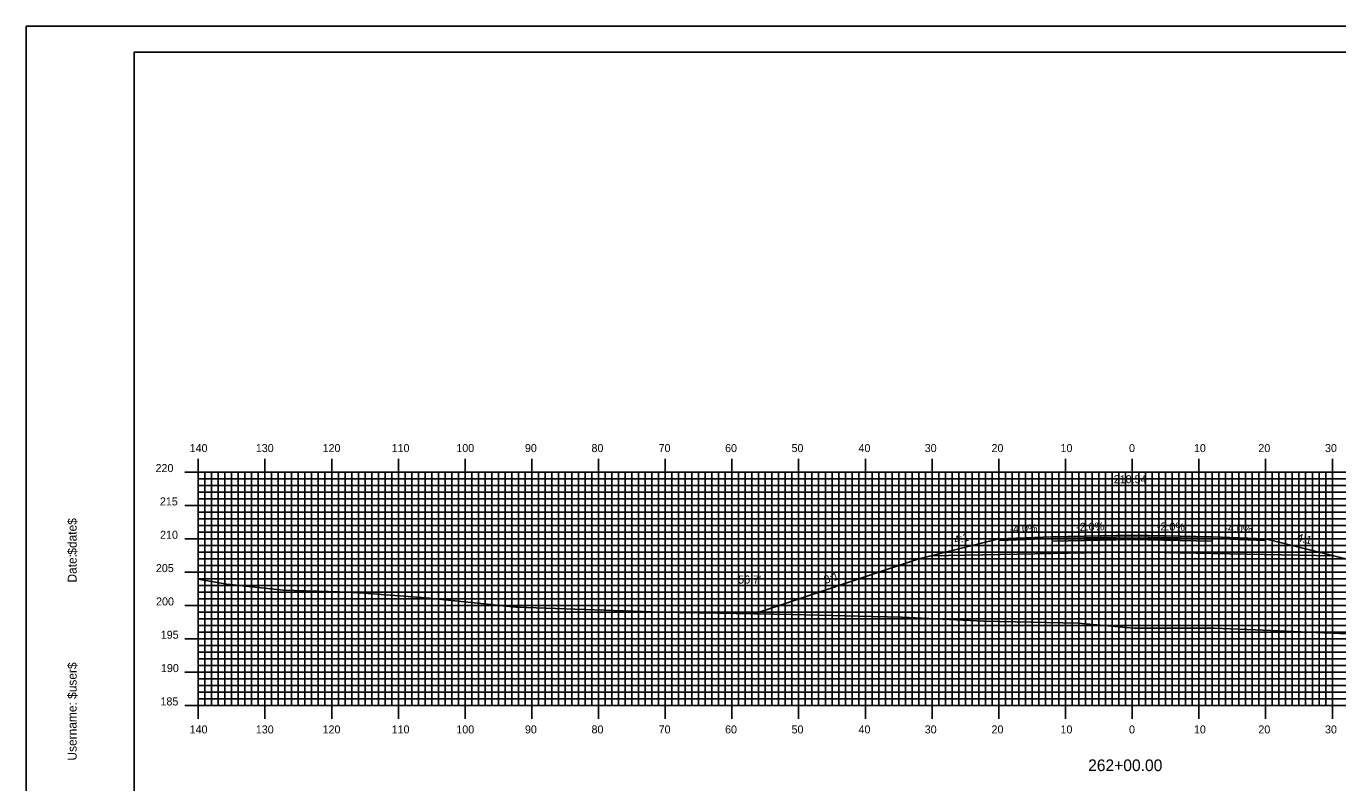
# Model space of a CAD drawing. Extents: x 1806258 to 1806601, y 442591 to 442811.
# Drawn here: x 1806257.9 to 1806454.5, y 442697.1 to 442810.5 of the extents above; entities that cross this region are included whole.
import ezdxf

# ---------------------------------------------------------------- set-up
doc = ezdxf.new("R2010")
doc.units = 0
for name, color, linetype in [('ANNOTATION', 7, 'Continuous'), ('BORDER', 7, 'Continuous'), ('D_Roadway_Centerline', 7, 'Continuous'), ('D_Roadway_Centerline_Text', 7, 'Continuous'), ('D_Roadway_Edge_Shoulder', 7, 'Continuous'), ('D_Roadway_Edge_TW', 7, 'Continuous'), ('D_Roadway_Pavement', 7, 'Continuous'), ('D_Roadway_SlopeLines', 7, 'Continuous'), ('D_Roadway_SubGrade', 7, 'Continuous'), ('D_Text_Standard', 7, 'Continuous'), ('H_V ANNOTATION', 7, 'Continuous'), ('MAJOR', 7, 'Continuous'), ('MINOR', 7, 'Continuous'), ('PLOT BOUNDARY', 7, 'Continuous'), ('S_Roadway_Centerline', 7, 'Continuous')]:
    doc.layers.add(name, color=color, linetype=linetype)

msp = doc.modelspace()

# ---------------------------------------------------------------- linework, layer by layer
at = {"layer": 'BORDER'}
msp.add_lwpolyline([(1806274.13, 442596.67), (1806594.13, 442596.67), (1806594.13, 442806.67), (1806274.13, 442806.67)], close=True, dxfattribs=at)
at = {"layer": 'D_Roadway_Centerline'}
msp.add_lwpolyline([(1806367.07, 442722.43), (1806391.73, 442730.65), (1806393.56, 442731.1), (1806403.73, 442733.65), (1806411.73, 442733.97), (1806423.73, 442734.21), (1806435.73, 442733.97), (1806443.73, 442733.65), (1806453.91, 442731.1), (1806455.73, 442730.65), (1806492.1, 442718.53)], dxfattribs=at)
at = {"layer": 'D_Roadway_Edge_Shoulder'}
for points in [[(1806411.73, 442733.97), (1806403.73, 442733.65), (1806403.73, 442733.4), (1806411.73, 442733.72)], [(1806435.73, 442733.97), (1806443.73, 442733.65), (1806443.73, 442733.4), (1806435.73, 442733.72)]]:
    msp.add_lwpolyline(points, close=True, dxfattribs=at)
at = {"layer": 'D_Roadway_Edge_TW'}
msp.add_lwpolyline([(1806411.73, 442733.72), (1806411.73, 442733.97), (1806423.73, 442734.21), (1806435.73, 442733.97), (1806435.73, 442733.72), (1806423.73, 442733.96)], close=True, dxfattribs=at)
at = {"layer": 'D_Roadway_Pavement'}
msp.add_lwpolyline([(1806411.73, 442733.3), (1806411.73, 442733.72), (1806423.73, 442733.96), (1806435.73, 442733.72), (1806435.73, 442733.3), (1806423.73, 442733.54)], close=True, dxfattribs=at)
at = {"layer": 'D_Roadway_SlopeLines'}
for points in [[(1806403.73, 442733.65), (1806391.73, 442730.65), (1806367.07, 442722.43)], [(1806443.73, 442733.65), (1806455.73, 442730.65), (1806492.1, 442718.53)]]:
    msp.add_lwpolyline(points, dxfattribs=at)
at = {"layer": 'D_Roadway_SubGrade'}
msp.add_lwpolyline([(1806411.73, 442731.47), (1806393.56, 442731.1), (1806403.73, 442733.65), (1806403.73, 442733.4), (1806411.73, 442733.72), (1806423.73, 442733.96), (1806435.73, 442733.72), (1806443.73, 442733.4), (1806443.73, 442733.65), (1806453.91, 442731.1), (1806435.73, 442731.47), (1806423.73, 442731.71)], close=True, dxfattribs=at)
at = {"layer": 'MAJOR'}
for p, q in [((1806283.73, 442745.67), (1806283.73, 442743.67)), ((1806293.73, 442745.67), (1806293.73, 442743.67)), ((1806303.73, 442745.67), (1806303.73, 442743.67)), ((1806313.73, 442745.67), (1806313.73, 442743.67)), ((1806323.73, 442745.67), (1806323.73, 442743.67)), ((1806333.73, 442745.67), (1806333.73, 442743.67)), ((1806343.73, 442745.67), (1806343.73, 442743.67)), ((1806353.73, 442745.67), (1806353.73, 442743.67)), ((1806363.73, 442745.67), (1806363.73, 442743.67)), ((1806373.73, 442745.67), (1806373.73, 442743.67)), ((1806383.73, 442745.67), (1806383.73, 442743.67)), ((1806393.73, 442745.67), (1806393.73, 442743.67)), ((1806403.73, 442745.67), (1806403.73, 442743.67)), ((1806413.73, 442745.67), (1806413.73, 442743.67)), ((1806423.73, 442745.67), (1806423.73, 442743.67)), ((1806433.73, 442745.67), (1806433.73, 442743.67)), ((1806443.73, 442745.67), (1806443.73, 442743.67)), ((1806453.73, 442745.67), (1806453.73, 442743.67)), ((1806281.73, 442743.67), (1806283.73, 442743.67)), ((1806283.73, 442743.67), (1806563.73, 442743.67)), ((1806283.73, 442708.67), (1806283.73, 442743.67)), ((1806283.73, 442708.67), (1806283.73, 442743.67)), ((1806283.73, 442743.67), (1806563.73, 442743.67)), ((1806293.73, 442708.67), (1806293.73, 442743.67)), ((1806303.73, 442708.67), (1806303.73, 442743.67)), ((1806313.73, 442708.67), (1806313.73, 442743.67)), ((1806323.73, 442708.67), (1806323.73, 442743.67)), ((1806333.73, 442708.67), (1806333.73, 442743.67)), ((1806343.73, 442708.67), (1806343.73, 442743.67)), ((1806353.73, 442708.67), (1806353.73, 442743.67)), ((1806363.73, 442708.67), (1806363.73, 442743.67)), ((1806373.73, 442708.67), (1806373.73, 442743.67)), ((1806383.73, 442708.67), (1806383.73, 442743.67)), ((1806393.73, 442708.67), (1806393.73, 442743.67)), ((1806403.73, 442708.67), (1806403.73, 442743.67)), ((1806413.73, 442708.67), (1806413.73, 442743.67)), ((1806423.73, 442708.67), (1806423.73, 442743.67)), ((1806433.73, 442708.67), (1806433.73, 442743.67)), ((1806443.73, 442708.67), (1806443.73, 442743.67)), ((1806453.73, 442708.67), (1806453.73, 442743.67)), ((1806281.73, 442738.67), (1806283.73, 442738.67)), ((1806283.73, 442738.67), (1806563.73, 442738.67)), ((1806281.73, 442733.67), (1806283.73, 442733.67)), ((1806283.73, 442733.67), (1806563.73, 442733.67)), ((1806281.73, 442728.67), (1806283.73, 442728.67)), ((1806283.73, 442728.67), (1806563.73, 442728.67)), ((1806281.73, 442723.67), (1806283.73, 442723.67)), ((1806283.73, 442723.67), (1806563.73, 442723.67)), ((1806281.73, 442718.67), (1806283.73, 442718.67)), ((1806283.73, 442718.67), (1806563.73, 442718.67)), ((1806281.73, 442713.67), (1806283.73, 442713.67)), ((1806283.73, 442713.67), (1806563.73, 442713.67)), ((1806281.73, 442708.67), (1806283.73, 442708.67)), ((1806283.73, 442708.67), (1806563.73, 442708.67)), ((1806283.73, 442708.67), (1806563.73, 442708.67)), ((1806283.73, 442706.66), (1806283.73, 442708.67)), ((1806293.73, 442706.66), (1806293.73, 442708.67)), ((1806303.73, 442706.66), (1806303.73, 442708.67)), ((1806313.73, 442706.66), (1806313.73, 442708.67)), ((1806323.73, 442706.66), (1806323.73, 442708.67)), ((1806333.73, 442706.66), (1806333.73, 442708.67)), ((1806343.73, 442706.66), (1806343.73, 442708.67)), ((1806353.73, 442706.66), (1806353.73, 442708.67)), ((1806363.73, 442706.66), (1806363.73, 442708.67)), ((1806373.73, 442706.66), (1806373.73, 442708.67)), ((1806383.73, 442706.66), (1806383.73, 442708.67)), ((1806393.73, 442706.66), (1806393.73, 442708.67)), ((1806403.73, 442706.66), (1806403.73, 442708.67)), ((1806413.73, 442706.66), (1806413.73, 442708.67)), ((1806423.73, 442706.66), (1806423.73, 442708.67)), ((1806433.73, 442706.66), (1806433.73, 442708.67)), ((1806443.73, 442706.66), (1806443.73, 442708.67)), ((1806453.73, 442706.66), (1806453.73, 442708.67))]:
    msp.add_line(p, q, dxfattribs=at)
at = {"layer": 'MINOR'}
for p, q in [((1806284.73, 442708.67), (1806284.73, 442743.67)), ((1806285.73, 442708.67), (1806285.73, 442743.67)), ((1806286.73, 442708.67), (1806286.73, 442743.67)), ((1806287.73, 442708.67), (1806287.73, 442743.67)), ((1806288.73, 442708.67), (1806288.73, 442743.67)), ((1806289.73, 442708.67), (1806289.73, 442743.67)), ((1806290.73, 442708.67), (1806290.73, 442743.67)), ((1806291.73, 442708.67), (1806291.73, 442743.67)), ((1806292.73, 442708.67), (1806292.73, 442743.67)), ((1806294.73, 442708.67), (1806294.73, 442743.67)), ((1806295.73, 442708.67), (1806295.73, 442743.67)), ((1806296.73, 442708.67), (1806296.73, 442743.67)), ((1806297.73, 442708.67), (1806297.73, 442743.67)), ((1806298.73, 442708.67), (1806298.73, 442743.67)), ((1806299.73, 442708.67), (1806299.73, 442743.67)), ((1806300.73, 442708.67), (1806300.73, 442743.67)), ((1806301.73, 442708.67), (1806301.73, 442743.67)), ((1806302.73, 442708.67), (1806302.73, 442743.67)), ((1806304.73, 442708.67), (1806304.73, 442743.67)), ((1806305.73, 442708.67), (1806305.73, 442743.67)), ((1806306.73, 442708.67), (1806306.73, 442743.67)), ((1806307.73, 442708.67), (1806307.73, 442743.67)), ((1806308.73, 442708.67), (1806308.73, 442743.67)), ((1806309.73, 442708.67), (1806309.73, 442743.67)), ((1806310.73, 442708.67), (1806310.73, 442743.67)), ((1806311.73, 442708.67), (1806311.73, 442743.67)), ((1806312.73, 442708.67), (1806312.73, 442743.67)), ((1806314.73, 442708.67), (1806314.73, 442743.67)), ((1806315.73, 442708.67), (1806315.73, 442743.67)), ((1806316.73, 442708.67), (1806316.73, 442743.67)), ((1806317.73, 442708.67), (1806317.73, 442743.67)), ((1806318.73, 442708.67), (1806318.73, 442743.67)), ((1806319.73, 442708.67), (1806319.73, 442743.67)), ((1806320.73, 442708.67), (1806320.73, 442743.67)), ((1806321.73, 442708.67), (1806321.73, 442743.67)), ((1806322.73, 442708.67), (1806322.73, 442743.67)), ((1806324.73, 442708.67), (1806324.73, 442743.67)), ((1806325.73, 442708.67), (1806325.73, 442743.67)), ((1806326.73, 442708.67), (1806326.73, 442743.67)), ((1806327.73, 442708.67), (1806327.73, 442743.67)), ((1806328.73, 442708.67), (1806328.73, 442743.67)), ((1806329.73, 442708.67), (1806329.73, 442743.67)), ((1806330.73, 442708.67), (1806330.73, 442743.67)), ((1806331.73, 442708.67), (1806331.73, 442743.67)), ((1806332.73, 442708.67), (1806332.73, 442743.67)), ((1806334.73, 442708.67), (1806334.73, 442743.67)), ((1806335.73, 442708.67), (1806335.73, 442743.67)), ((1806336.73, 442708.67), (1806336.73, 442743.67)), ((1806337.73, 442708.67), (1806337.73, 442743.67)), ((1806338.73, 442708.67), (1806338.73, 442743.67)), ((1806339.73, 442708.67), (1806339.73, 442743.67)), ((1806340.73, 442708.67), (1806340.73, 442743.67)), ((1806341.73, 442708.67), (1806341.73, 442743.67)), ((1806342.73, 442708.67), (1806342.73, 442743.67)), ((1806344.73, 442708.67), (1806344.73, 442743.67)), ((1806345.73, 442708.67), (1806345.73, 442743.67)), ((1806346.73, 442708.67), (1806346.73, 442743.67)), ((1806347.73, 442708.67), (1806347.73, 442743.67)), ((1806348.73, 442708.67), (1806348.73, 442743.67)), ((1806349.73, 442708.67), (1806349.73, 442743.67)), ((1806350.73, 442708.67), (1806350.73, 442743.67)), ((1806351.73, 442708.67), (1806351.73, 442743.67)), ((1806352.73, 442708.67), (1806352.73, 442743.67)), ((1806354.73, 442708.67), (1806354.73, 442743.67)), ((1806355.73, 442708.67), (1806355.73, 442743.67)), ((1806356.73, 442708.67), (1806356.73, 442743.67)), ((1806357.73, 442708.67), (1806357.73, 442743.67)), ((1806358.73, 442708.67), (1806358.73, 442743.67)), ((1806359.73, 442708.67), (1806359.73, 442743.67)), ((1806360.73, 442708.67), (1806360.73, 442743.67)), ((1806361.73, 442708.67), (1806361.73, 442743.67)), ((1806362.73, 442708.67), (1806362.73, 442743.67)), ((1806364.73, 442708.67), (1806364.73, 442743.67)), ((1806365.73, 442708.67), (1806365.73, 442743.67)), ((1806366.73, 442708.67), (1806366.73, 442743.67)), ((1806367.73, 442708.67), (1806367.73, 442743.67)), ((1806368.73, 442708.67), (1806368.73, 442743.67)), ((1806369.73, 442708.67), (1806369.73, 442743.67)), ((1806370.73, 442708.67), (1806370.73, 442743.67)), ((1806371.73, 442708.67), (1806371.73, 442743.67)), ((1806372.73, 442708.67), (1806372.73, 442743.67)), ((1806374.73, 442708.67), (1806374.73, 442743.67)), ((1806375.73, 442708.67), (1806375.73, 442743.67)), ((1806376.73, 442708.67), (1806376.73, 442743.67)), ((1806377.73, 442708.67), (1806377.73, 442743.67)), ((1806378.73, 442708.67), (1806378.73, 442743.67)), ((1806379.73, 442708.67), (1806379.73, 442743.67)), ((1806380.73, 442708.67), (1806380.73, 442743.67)), ((1806381.73, 442708.67), (1806381.73, 442743.67)), ((1806382.73, 442708.67), (1806382.73, 442743.67)), ((1806384.73, 442708.67), (1806384.73, 442743.67)), ((1806385.73, 442708.67), (1806385.73, 442743.67)), ((1806386.73, 442708.67), (1806386.73, 442743.67)), ((1806387.73, 442708.67), (1806387.73, 442743.67)), ((1806388.73, 442708.67), (1806388.73, 442743.67)), ((1806389.73, 442708.67), (1806389.73, 442743.67)), ((1806390.73, 442708.67), (1806390.73, 442743.67)), ((1806391.73, 442708.67), (1806391.73, 442743.67)), ((1806392.73, 442708.67), (1806392.73, 442743.67)), ((1806394.73, 442708.67), (1806394.73, 442743.67)), ((1806395.73, 442708.67), (1806395.73, 442743.67)), ((1806396.73, 442708.67), (1806396.73, 442743.67)), ((1806397.73, 442708.67), (1806397.73, 442743.67)), ((1806398.73, 442708.67), (1806398.73, 442743.67)), ((1806399.73, 442708.67), (1806399.73, 442743.67)), ((1806400.73, 442708.67), (1806400.73, 442743.67)), ((1806401.73, 442708.67), (1806401.73, 442743.67)), ((1806402.73, 442708.67), (1806402.73, 442743.67)), ((1806404.73, 442708.67), (1806404.73, 442743.67)), ((1806405.73, 442708.67), (1806405.73, 442743.67)), ((1806406.73, 442708.67), (1806406.73, 442743.67)), ((1806407.73, 442708.67), (1806407.73, 442743.67)), ((1806408.73, 442708.67), (1806408.73, 442743.67)), ((1806409.73, 442708.67), (1806409.73, 442743.67)), ((1806410.73, 442708.67), (1806410.73, 442743.67)), ((1806411.73, 442708.67), (1806411.73, 442743.67)), ((1806412.73, 442708.67), (1806412.73, 442743.67)), ((1806414.73, 442708.67), (1806414.73, 442743.67)), ((1806415.73, 442708.67), (1806415.73, 442743.67)), ((1806416.73, 442708.67), (1806416.73, 442743.67)), ((1806417.73, 442708.67), (1806417.73, 442743.67)), ((1806418.73, 442708.67), (1806418.73, 442743.67)), ((1806419.73, 442708.67), (1806419.73, 442743.67)), ((1806420.73, 442708.67), (1806420.73, 442743.67)), ((1806421.73, 442708.67), (1806421.73, 442743.67)), ((1806422.73, 442708.67), (1806422.73, 442743.67)), ((1806424.73, 442708.67), (1806424.73, 442743.67)), ((1806425.73, 442708.67), (1806425.73, 442743.67)), ((1806426.73, 442708.67), (1806426.73, 442743.67)), ((1806427.73, 442708.67), (1806427.73, 442743.67)), ((1806428.73, 442708.67), (1806428.73, 442743.67)), ((1806429.73, 442708.67), (1806429.73, 442743.67)), ((1806430.73, 442708.67), (1806430.73, 442743.67)), ((1806431.73, 442708.67), (1806431.73, 442743.67)), ((1806432.73, 442708.67), (1806432.73, 442743.67)), ((1806434.73, 442708.67), (1806434.73, 442743.67)), ((1806435.73, 442708.67), (1806435.73, 442743.67)), ((1806436.73, 442708.67), (1806436.73, 442743.67)), ((1806437.73, 442708.67), (1806437.73, 442743.67)), ((1806438.73, 442708.67), (1806438.73, 442743.67)), ((1806439.73, 442708.67), (1806439.73, 442743.67)), ((1806440.73, 442708.67), (1806440.73, 442743.67)), ((1806441.73, 442708.67), (1806441.73, 442743.67)), ((1806442.73, 442708.67), (1806442.73, 442743.67)), ((1806444.73, 442708.67), (1806444.73, 442743.67)), ((1806445.73, 442708.67), (1806445.73, 442743.67)), ((1806446.73, 442708.67), (1806446.73, 442743.67)), ((1806447.73, 442708.67), (1806447.73, 442743.67)), ((1806448.73, 442708.67), (1806448.73, 442743.67)), ((1806449.73, 442708.67), (1806449.73, 442743.67)), ((1806450.73, 442708.67), (1806450.73, 442743.67)), ((1806451.73, 442708.67), (1806451.73, 442743.67)), ((1806452.73, 442708.67), (1806452.73, 442743.67)), ((1806283.73, 442742.67), (1806563.73, 442742.67)), ((1806283.73, 442742.67), (1806285.74, 442742.67)), ((1806283.73, 442741.67), (1806563.73, 442741.67)), ((1806283.73, 442741.67), (1806285.74, 442741.67)), ((1806283.73, 442740.67), (1806563.73, 442740.67)), ((1806283.73, 442740.67), (1806285.74, 442740.67)), ((1806283.73, 442739.67), (1806563.73, 442739.67)), ((1806283.73, 442739.67), (1806285.74, 442739.67)), ((1806283.73, 442737.67), (1806563.73, 442737.67)), ((1806283.73, 442737.67), (1806285.74, 442737.67)), ((1806283.73, 442736.67), (1806563.73, 442736.67)), ((1806283.73, 442736.67), (1806285.74, 442736.67)), ((1806283.73, 442735.67), (1806563.73, 442735.67)), ((1806283.73, 442735.67), (1806285.74, 442735.67)), ((1806283.73, 442734.67), (1806563.73, 442734.67)), ((1806283.73, 442734.67), (1806285.74, 442734.67)), ((1806283.73, 442732.67), (1806563.73, 442732.67)), ((1806283.73, 442732.67), (1806285.74, 442732.67)), ((1806283.73, 442731.67), (1806563.73, 442731.67)), ((1806283.73, 442731.67), (1806285.74, 442731.67)), ((1806283.73, 442730.67), (1806563.73, 442730.67)), ((1806283.73, 442730.67), (1806285.74, 442730.67)), ((1806283.73, 442729.67), (1806563.73, 442729.67)), ((1806283.73, 442729.67), (1806285.74, 442729.67)), ((1806283.73, 442727.67), (1806563.73, 442727.67)), ((1806283.73, 442727.67), (1806285.74, 442727.67)), ((1806283.73, 442726.67), (1806563.73, 442726.67)), ((1806283.73, 442726.67), (1806285.74, 442726.67)), ((1806283.73, 442725.67), (1806563.73, 442725.67)), ((1806283.73, 442725.67), (1806285.74, 442725.67)), ((1806283.73, 442724.67), (1806563.73, 442724.67)), ((1806283.73, 442724.67), (1806285.74, 442724.67)), ((1806283.73, 442722.67), (1806563.73, 442722.67)), ((1806283.73, 442722.67), (1806285.74, 442722.67)), ((1806283.73, 442721.67), (1806563.73, 442721.67)), ((1806283.73, 442721.67), (1806285.74, 442721.67)), ((1806283.73, 442720.67), (1806563.73, 442720.67)), ((1806283.73, 442720.67), (1806285.74, 442720.67)), ((1806283.73, 442719.67), (1806563.73, 442719.67)), ((1806283.73, 442719.67), (1806285.74, 442719.67)), ((1806283.73, 442717.67), (1806563.73, 442717.67)), ((1806283.73, 442717.67), (1806285.74, 442717.67)), ((1806283.73, 442716.67), (1806563.73, 442716.67)), ((1806283.73, 442716.67), (1806285.74, 442716.67)), ((1806283.73, 442715.67), (1806563.73, 442715.67)), ((1806283.73, 442715.67), (1806285.74, 442715.67)), ((1806283.73, 442714.67), (1806563.73, 442714.67)), ((1806283.73, 442714.67), (1806285.74, 442714.67)), ((1806283.73, 442712.67), (1806563.73, 442712.67)), ((1806283.73, 442712.67), (1806285.74, 442712.67)), ((1806283.73, 442711.67), (1806563.73, 442711.67)), ((1806283.73, 442711.67), (1806285.74, 442711.67)), ((1806283.73, 442710.67), (1806563.73, 442710.67)), ((1806283.73, 442710.67), (1806285.74, 442710.67)), ((1806283.73, 442709.67), (1806563.73, 442709.67)), ((1806283.73, 442709.67), (1806285.74, 442709.67))]:
    msp.add_line(p, q, dxfattribs=at)
at = {"layer": 'PLOT BOUNDARY'}
msp.add_lwpolyline([(1806257.95, 442590.55), (1806597.95, 442590.55), (1806597.95, 442810.55), (1806257.95, 442810.55)], close=True, dxfattribs=at)
at = {"layer": 'S_Roadway_Centerline'}
msp.add_lwpolyline([(1806283.73, 442727.59), (1806288.03, 442726.88), (1806296.44, 442725.94), (1806304.93, 442725.69), (1806308.57, 442725.52), (1806317.84, 442724.82), (1806331.4, 442723.43), (1806331.61, 442723.42), (1806331.75, 442723.4), (1806332.95, 442723.36), (1806353.29, 442722.65), (1806355.92, 442722.63), (1806372.81, 442722.32), (1806382.65, 442722.07), (1806389.17, 442721.89), (1806401.51, 442721.33), (1806415.66, 442720.99), (1806423.99, 442720.25), (1806434.69, 442720.27), (1806436.02, 442720.27), (1806442.15, 442720.01), (1806457.09, 442719.38)], dxfattribs=at)

# ---------------------------------------------------------------- texts
at = {"layer": 'ANNOTATION'}
for s, rotation, p in [('-4.0%', 2.2906, (1806405.36, 442734.51)), ('-2.0%', 1.1458, (1806415.34, 442734.84)), ('-2.0%', 358.8542, (1806427.42, 442734.93)), ('-4.0%', 357.7094, (1806437.52, 442734.7)), ('4:1', 14.0362, (1806397.18, 442732.87)), ('4:1', 345.9638, (1806448.33, 442733.36)), ('3:1', 18.4348, (1806377.74, 442726.89))]:
    msp.add_text(s, height=1.2, rotation=rotation, dxfattribs=at).set_placement(p)
at = {"layer": 'BORDER'}
for s, p in [('$date$', (1806265.5, 442731.28)), ('Date:', (1806265.5, 442727.1)), ('$user$', (1806265.5, 442709.65)), ('Username:', (1806265.5, 442700.4))]:
    msp.add_text(s, height=1.339, rotation=90, dxfattribs=at).set_placement(p)
at = {"layer": 'D_Roadway_Centerline'}
for s, p in [('C', (1806423.73, 442734.21)), ('L', (1806423.73, 442734.2))]:
    msp.add_text(s, height=0.0146, dxfattribs=at).set_placement(p)
at = {"layer": 'D_Roadway_Centerline_Text'}
msp.add_text('210.54', height=1.2, dxfattribs=at).set_placement((1806420.97, 442742))
at = {"layer": 'D_Text_Standard'}
msp.add_text("56.7'", height=1.2, dxfattribs=at).set_placement((1806364.67, 442726.95))
at = {"layer": 'H_V ANNOTATION'}
for s, height, p in [('140', 1.2, (1806282.44, 442746.67)), ('130', 1.2, (1806292.36, 442746.67)), ('120', 1.2, (1806302.37, 442746.67)), ('110', 1.2, (1806312.72, 442746.67)), ('100', 1.2, (1806322.42, 442746.67)), ('90', 1.2, (1806332.7, 442746.67)), ('80', 1.2, (1806342.68, 442746.67)), ('70', 1.2, (1806352.74, 442746.67)), ('60', 1.2, (1806362.7, 442746.67)), ('50', 1.2, (1806372.66, 442746.67)), ('40', 1.2, (1806382.7, 442746.67)), ('30', 1.2, (1806392.63, 442746.67)), ('20', 1.2, (1806402.64, 442746.67)), ('10', 1.2, (1806412.98, 442746.67)), ('0', 1.2, (1806423.25, 442746.67)), ('10', 1.2, (1806432.98, 442746.67)), ('20', 1.2, (1806442.64, 442746.67)), ('30', 1.2, (1806452.63, 442746.67)), ('220', 1.2, (1806277.33, 442743.67)), ('215', 1.2, (1806277.98, 442738.67)), ('210', 1.2, (1806278.01, 442733.67)), ('205', 1.2, (1806277.38, 442728.67)), ('200', 1.2, (1806277.41, 442723.67)), ('195', 1.2, (1806278.11, 442718.67)), ('190', 1.2, (1806278.14, 442713.67)), ('185', 1.2, (1806278.07, 442708.67)), ('140', 1.2, (1806282.44, 442704.47)), ('130', 1.2, (1806292.36, 442704.47)), ('120', 1.2, (1806302.37, 442704.47)), ('110', 1.2, (1806312.72, 442704.47)), ('100', 1.2, (1806322.42, 442704.47)), ('90', 1.2, (1806332.7, 442704.47)), ('80', 1.2, (1806342.68, 442704.47)), ('70', 1.2, (1806352.74, 442704.47)), ('60', 1.2, (1806362.7, 442704.47)), ('50', 1.2, (1806372.66, 442704.47)), ('40', 1.2, (1806382.7, 442704.47)), ('30', 1.2, (1806392.63, 442704.47)), ('20', 1.2, (1806402.64, 442704.47)), ('10', 1.2, (1806412.98, 442704.47)), ('0', 1.2, (1806423.25, 442704.47)), ('10', 1.2, (1806432.98, 442704.47)), ('20', 1.2, (1806442.64, 442704.47)), ('30', 1.2, (1806452.63, 442704.47)), ('262+00.00', 1.75, (1806417.12, 442698.82))]:
    msp.add_text(s, height=height, dxfattribs=at).set_placement(p)
at = {"layer": 'MAJOR'}
msp.add_text('-', height=0.012, dxfattribs=at).set_placement((1806283.72, 442708.67))

doc.saveas('drawing.dxf')
